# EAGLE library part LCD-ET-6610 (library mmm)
ET-LCD6610: 132x132 color graphic display www.gravitech.us
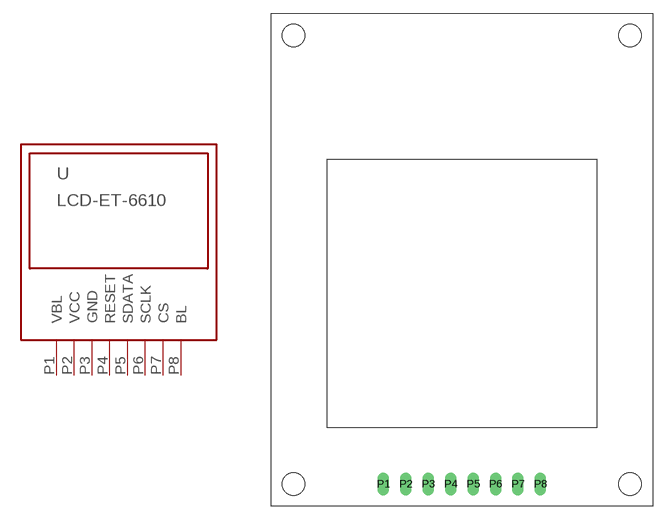
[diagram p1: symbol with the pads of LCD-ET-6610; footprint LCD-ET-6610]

Designator prefix -

## LCD-ET-6610  [LCD-ET-6610]
P1  VBL  pas
P2  VCC  pas
P3  GND  pas
P4  RESET  in
P5  SDATA  in
P6  SCLK  in
P7  CS  in
P8  BL  in

## Footprint LCD-ET-6610 (pad centres in mm)
drill 0.8 long: P1 -8.89,-25.4; P2 -6.35,-25.4; P3 -3.81,-25.4; P4 -1.27,-25.4; P5 1.27,-25.4; P6 3.81,-25.4; P7 6.35,-25.4; P8 8.89,-25.4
